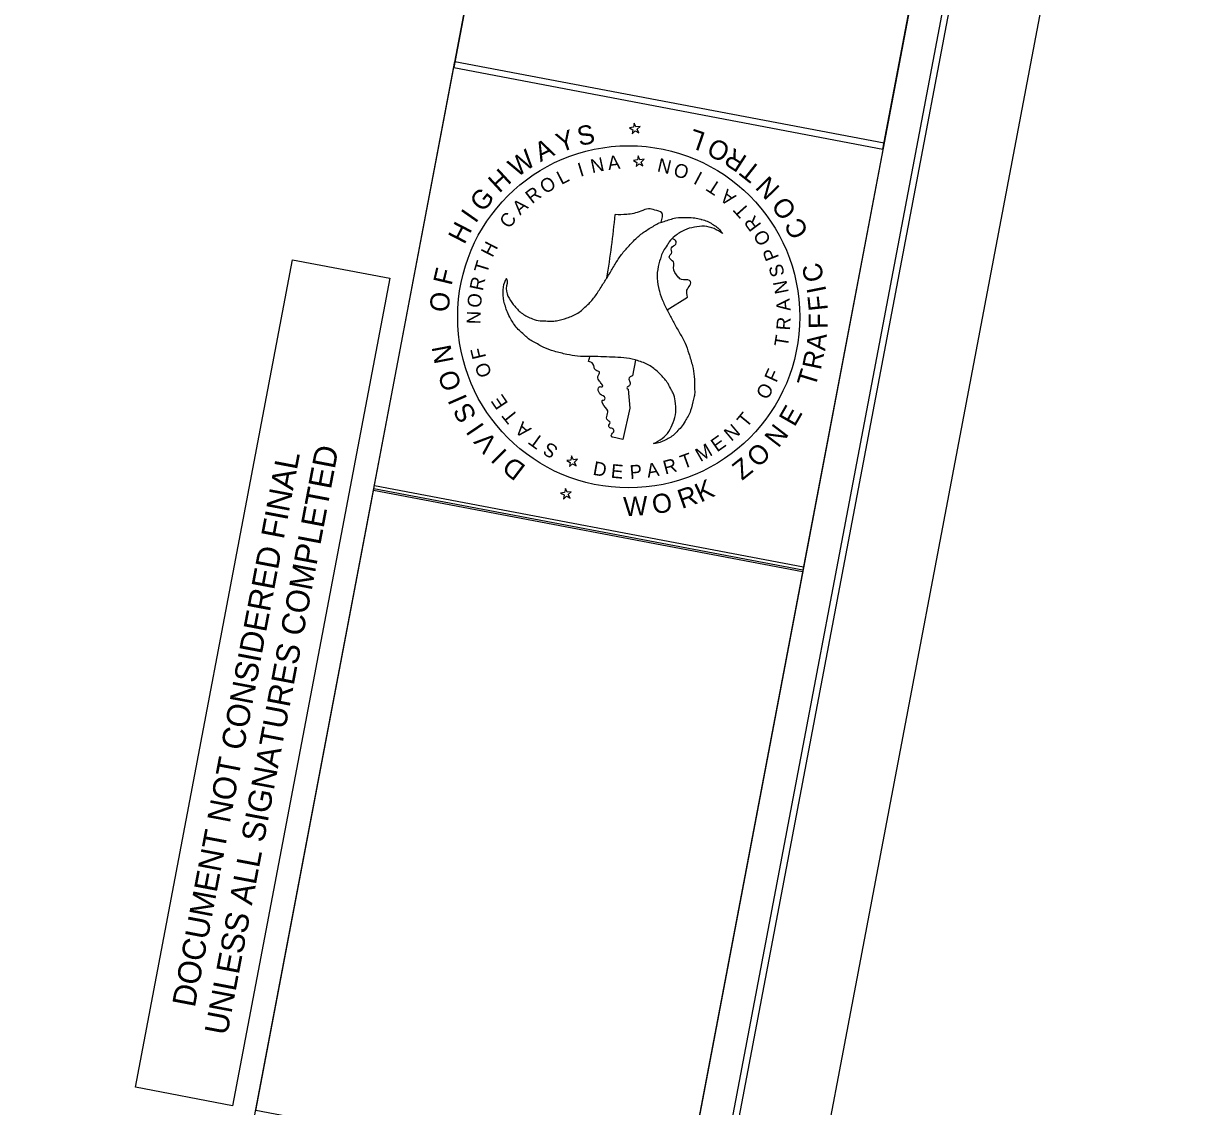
# Model space of a CAD drawing. Extents: x 1615680 to 1619687, y 899305 to 902270.
# Drawn here: x 1619375.5 to 1619686.6, y 901546.7 to 901831.9 of the extents above; entities that cross this region are included whole.
import ezdxf

# ---------------------------------------------------------------- set-up
doc = ezdxf.new("R2010")
doc.units = 0
for name, color, linetype in [('Prop Mkg Solid Yel Skip RT Rpm 80ft', 7, 'Continuous'), ('Scratch_Level_3', 7, 'Continuous'), ('Stage 5', 7, 'Continuous'), ('Stage 6', 7, 'Continuous')]:
    doc.layers.add(name, color=color, linetype=linetype)

msp = doc.modelspace()

# ---------------------------------------------------------------- linework, layer by layer
at = {"layer": 'Scratch_Level_3'}
for p, q in [((1619536.39, 901805.73), (1619536.19, 901804.66)), ((1619536.86, 901804.74), (1619536.39, 901805.73)), ((1619536.19, 901804.66), (1619535.13, 901804.49)), ((1619535.13, 901804.49), (1619536.06, 901803.99)), ((1619536.06, 901803.99), (1619535.86, 901802.92)), ((1619535.86, 901802.92), (1619536.66, 901803.67)), ((1619536.66, 901803.67), (1619537.62, 901803.16)), ((1619537.95, 901804.86), (1619536.86, 901804.74)), ((1619537.15, 901804.11), (1619537.95, 901804.86)), ((1619537.62, 901803.16), (1619537.15, 901804.11)), ((1619537.24, 901796.02), (1619536.19, 901795.85)), ((1619536.19, 901795.85), (1619537.12, 901795.34)), ((1619537.45, 901797.08), (1619537.24, 901796.02)), ((1619537.91, 901796.09), (1619537.45, 901797.08)), ((1619539, 901796.21), (1619537.91, 901796.09)), ((1619538.2, 901795.46), (1619539, 901796.21)), ((1619537.12, 901795.34), (1619536.91, 901794.28)), ((1619536.91, 901794.28), (1619537.71, 901795.02)), ((1619537.71, 901795.02), (1619538.68, 901794.51)), ((1619538.68, 901794.51), (1619538.2, 901795.46)), ((1619545.07, 901756.54), (1619550.47, 901759.91)), ((1619536.04, 901739.13), (1619536.86, 901743.28)), ((1619534.79, 901735.6), (1619535.28, 901730.6)), ((1619535.28, 901730.6), (1619533.41, 901722.4)), ((1619533.41, 901722.4), (1619530.81, 901722.98)), ((1619519.9, 901718.03), (1619519.7, 901716.96)), ((1619520.37, 901717.04), (1619519.9, 901718.03)), ((1619519.7, 901716.96), (1619518.64, 901716.79)), ((1619518.64, 901716.79), (1619519.57, 901716.29)), ((1619519.57, 901716.29), (1619519.37, 901715.22)), ((1619519.37, 901715.22), (1619520.16, 901715.97)), ((1619520.16, 901715.97), (1619521.13, 901715.46)), ((1619521.45, 901717.16), (1619520.37, 901717.04)), ((1619520.66, 901716.41), (1619521.45, 901717.16)), ((1619521.13, 901715.46), (1619520.66, 901716.41)), ((1619518.26, 901709.49), (1619518.06, 901708.42)), ((1619518.73, 901708.5), (1619518.26, 901709.49)), ((1619518.73, 901708.5), (1619518.26, 901709.49)), ((1619519.82, 901708.62), (1619518.73, 901708.5)), ((1619519.82, 901708.62), (1619518.73, 901708.5)), ((1619519.02, 901707.87), (1619519.82, 901708.62)), ((1619519.02, 901707.87), (1619519.82, 901708.62)), ((1619518.06, 901708.42), (1619517, 901708.25)), ((1619517, 901708.25), (1619517.93, 901707.75)), ((1619517.93, 901707.75), (1619517.73, 901706.68)), ((1619517.73, 901706.68), (1619518.53, 901707.43)), ((1619517.73, 901706.68), (1619518.53, 901707.43)), ((1619518.53, 901707.43), (1619519.5, 901706.92)), ((1619518.53, 901707.43), (1619519.5, 901706.92)), ((1619519.5, 901706.92), (1619519.02, 901707.87)), ((1619519.5, 901706.92), (1619519.02, 901707.87))]:
    msp.add_line(p, q, dxfattribs=at)
msp.add_circle((1619534.96, 901754.69), 45.07, dxfattribs=at)
for start, end in [(350.4529, 354.5729), (344.9279, 345.2256)]:
    msp.add_arc((1619298.76, 901803.71), 233.68, start, end, dxfattribs=at)
for points in [[(1619502.64, 901764.83), (1619502.71, 901764.74), (1619502.7, 901762.11), (1619503.45, 901759.58), (1619504.91, 901757.47), (1619506.93, 901755.53), (1619509.57, 901754.15), (1619511.63, 901753.62), (1619512.67, 901753.62), (1619514.46, 901753.53), (1619515.91, 901753.66), (1619518.71, 901754.42), (1619521.52, 901755.66), (1619524.02, 901757.76), (1619524.22, 901757.94), (1619526.16, 901760.2), (1619527.86, 901762.81), (1619529.43, 901765.3), (1619531, 901767.94), (1619532.64, 901770.52), (1619534.49, 901772.8), (1619536.82, 901775.24), (1619539.06, 901777.08), (1619541.69, 901778.72), (1619543.01, 901779.45), (1619544.29, 901779.84), (1619547.34, 901780.74), (1619550.48, 901780.86), (1619552.37, 901780.74), (1619553.95, 901780.39), (1619554.22, 901780.34), (1619556.97, 901779.13), (1619559.16, 901777.38), (1619559.7, 901776.62)], [(1619543.49, 901779.62), (1619543.65, 901782.11), (1619541.8, 901782.83), (1619540.19, 901783.16), (1619538.13, 901782.52), (1619534.43, 901781.67), (1619531.39, 901781.61)], [(1619559.7, 901776.62), (1619557.43, 901777.92), (1619554.89, 901778.54), (1619552.3, 901778.32), (1619549.61, 901777.54), (1619547.12, 901775.96), (1619545.62, 901774.44), (1619545.09, 901773.53), (1619544.1, 901772.07), (1619543.51, 901770.68), (1619542.74, 901767.92), (1619542.43, 901764.83), (1619543, 901761.63), (1619543.06, 901761.37), (1619544.08, 901758.55), (1619545.45, 901755.8), (1619546.81, 901753.16), (1619548.33, 901750.49), (1619549.79, 901747.77), (1619550.8, 901745.03), (1619551.74, 901741.79), (1619552.21, 901738.93), (1619552.31, 901735.85), (1619552.3, 901734.32), (1619552, 901733.03), (1619551.25, 901729.97), (1619549.79, 901727.16), (1619548.75, 901725.6), (1619547.62, 901724.42), (1619547.45, 901724.21), (1619545.05, 901722.41), (1619542.45, 901721.4), (1619541.47, 901721.29)], [(1619550.47, 901759.91), (1619550.29, 901761.68), (1619551.08, 901762.97), (1619551.32, 901763.61), (1619551.01, 901764.25), (1619548.89, 901764.48), (1619548.01, 901765.14), (1619546.77, 901767.71), (1619546.72, 901769.16), (1619545.64, 901770.43), (1619545.75, 901770.84), (1619546.23, 901771.41), (1619546.22, 901772.88), (1619547.36, 901773.85), (1619547.43, 901774.53), (1619546.48, 901775.26)], [(1619541.47, 901721.29), (1619543.78, 901722.63), (1619545.56, 901724.51), (1619546.66, 901726.85), (1619547.35, 901729.59), (1619547.22, 901732.54), (1619546.63, 901734.6), (1619546.14, 901735.51), (1619545.32, 901737.09), (1619544.45, 901738.27), (1619542.43, 901740.35), (1619539.93, 901742.14), (1619536.88, 901743.27), (1619536.62, 901743.35), (1619533.66, 901743.88), (1619530.6, 901744.05), (1619527.63, 901744.18), (1619524.55, 901744.21), (1619521.5, 901744.3), (1619518.61, 901744.79), (1619515.34, 901745.61), (1619512.6, 901746.62), (1619509.87, 901748.1), (1619508.59, 901748.86), (1619507.61, 901749.76), (1619505.32, 901751.97), (1619503.64, 901754.62), (1619502.8, 901756.31), (1619502.33, 901757.85), (1619502.24, 901758.12), (1619501.88, 901761.09), (1619502.29, 901763.86), (1619502.71, 901764.74)], [(1619530.81, 901722.98), (1619530.54, 901722.94), (1619530.35, 901723.44), (1619531.08, 901724.57), (1619530.67, 901725.28), (1619530.14, 901725.35), (1619529.7, 901725.96), (1619530.03, 901726.76), (1619529.22, 901727.69), (1619529.16, 901728.42), (1619529.44, 901729.9), (1619528.02, 901731.98), (1619528.05, 901732.72), (1619528.56, 901732.83), (1619528.72, 901733.26), (1619527.43, 901734.31), (1619527.27, 901734.54), (1619526.97, 901735.98), (1619527.31, 901736.29), (1619527.97, 901736.28), (1619528.12, 901736.46), (1619527.9, 901736.96), (1619527.24, 901737.72), (1619526.86, 901738.94), (1619527.27, 901740.19), (1619526.26, 901740.62), (1619525.54, 901742.31), (1619524.99, 901742.73), (1619524.39, 901742.93)], [(1619536.04, 901739.13), (1619535.33, 901738.92), (1619535.01, 901738.29), (1619535.31, 901737.28), (1619535.16, 901736.62), (1619534.46, 901735.98), (1619534.79, 901735.6)]]:
    msp.add_spline(points, degree=3, dxfattribs=at)
at = {"layer": 'Stage 5'}
msp.add_lwpolyline([(1618277.81, 900596.04), (1618595.68, 902270.17), (1619686.64, 902063.03), (1619368.77, 900388.9)], close=True, dxfattribs=at)
at = {"layer": 'Stage 6'}
for p, q in [((1619404.98, 901551.7), (1619446.37, 901769.7)), ((1619446.38, 901769.7), (1619471.99, 901764.84)), ((1619471.98, 901764.84), (1619430.59, 901546.83)), ((1619467.81, 901709.47), (1619580.87, 901688.01)), ((1619430.59, 901546.83), (1619404.98, 901551.7))]:
    msp.add_line(p, q, dxfattribs=at)
for points in [[(1618300.12, 900599.5), (1618613.97, 902252.47), (1619660.79, 902053.71), (1619346.95, 900400.74)], [(1618615.64, 902240.02), (1618333.18, 900752.34), (1619374.55, 900554.62), (1619657.01, 902042.3)], [(1619436.39, 901543.98), (1619533.55, 902055.74), (1619646.62, 902034.27), (1619549.46, 901522.51)], [(1619533.31, 902054.43), (1619488.87, 901820.37), (1619601.93, 901798.9), (1619646.37, 902032.96)], [(1619467.71, 901708.94), (1619489.18, 901822), (1619602.24, 901800.54), (1619580.77, 901687.47)], [(1619436.7, 901545.61), (1619467.96, 901710.25), (1619581.02, 901688.78), (1619549.76, 901524.14)]]:
    msp.add_lwpolyline(points, close=True, dxfattribs=at)

# ---------------------------------------------------------------- texts
at = {"layer": 'Prop Mkg Solid Yel Skip RT Rpm 80ft'}
for s, rotation, p in [('L', 160.9615, (1619555.47, 901803.06)), ('O', 152.8217, (1619562.11, 901799.67)), ('R', 147.1239, (1619566.44, 901796.76)), ('T', 141.833, (1619570.19, 901793.67)), ('N', 134.1928, (1619575.06, 901788.64)), ('O', 126.053, (1619579.46, 901782.62)), ('C', 119.0972, (1619582.52, 901777.03)), ('C', 104.8156, (1619586.56, 901764.61)), ('I', 101.3192, (1619587.07, 901761.44)), ('F', 95.8989, (1619587.47, 901756.49)), ('F', 90.4785, (1619587.41, 901751.52)), ('A', 83.9667, (1619586.71, 901745.59)), ('R', 78.2689, (1619585.55, 901740.5)), ('T', 72.978, (1619584.03, 901735.89)), ('E', 60.1764, (1619578.65, 901725.49)), ('N', 52.5361, (1619574.38, 901719.94)), ('O', 44.3964, (1619569.06, 901714.71)), ('Z', 38.5691, (1619564.82, 901711.45)), ('K', 25.0644, (1619553.9, 901705.68)), ('R', 19.3666, (1619548.94, 901704.04)), ('W', 2.5043, (1619533.65, 901702.16)), ('O', 11.2268, (1619541.63, 901702.57))]:
    msp.add_text(s, height=5.05, rotation=rotation, dxfattribs=at).set_placement(p)
at = {"layer": 'Scratch_Level_3'}
for s, height, rotation, p in [('S', 5.05, 12.4743, (1619521.99, 901799.64)), ('Y', 5.05, 18.9977, (1619516.91, 901797.91)), ('W', 5.05, 35.0626, (1619505.52, 901791.3)), ('A', 5.05, 26.0256, (1619511.7, 901795.42)), ('N', 3.63, 12.1007, (1619525.33, 901792.51)), ('A', 3.63, 7.0227, (1619529.63, 901793.33)), ('N', 3.63, 166.9823, (1619546.5, 901795.79)), ('H', 5.05, 42.7126, (1619500.84, 901787.1)), ('L', 3.63, 27.335, (1619517.19, 901789.4)), ('I', 3.63, 17.1788, (1619522.19, 901791.56)), ('O', 3.63, 162.1763, (1619551.17, 901794.26)), ('I', 3.63, 152.0201, (1619554.67, 901792.49)), ('O', 3.63, 32.4131, (1619512.97, 901786.92)), ('T', 3.63, 146.942, (1619559.61, 901789.52)), ('G', 5.05, 50.7661, (1619496.57, 901782.04)), ('R', 3.63, 37.4912, (1619509.5, 901784.31)), ('A', 3.63, 141.8639, (1619563.46, 901786.51)), ('A', 3.63, 42.5693, (1619506.33, 901781.35)), ('T', 3.63, 131.7077, (1619566.99, 901782.83)), ('I', 5.05, 55.0534, (1619494.59, 901779.12)), ('C', 3.63, 52.7254, (1619503.47, 901777.71)), ('R', 3.63, 126.6297, (1619570.06, 901778.93)), ('H', 5.05, 62.7034, (1619491.63, 901773.57)), ('O', 3.63, 121.5516, (1619572.62, 901774.85)), ('H', 3.63, 62.8816, (1619499.06, 901770.15)), ('P', 3.63, 111.3954, (1619574.63, 901770.31)), ('F', 5.05, 76.5069, (1619488.26, 901762.75)), ('T', 3.63, 73.0378, (1619497.6, 901765.89)), ('S', 3.63, 106.3173, (1619576.13, 901765.81)), ('R', 3.63, 78.1158, (1619496.51, 901761.37)), ('N', 3.63, 101.2392, (1619577.15, 901761.12)), ('O', 5.05, 85.0143, (1619487.51, 901755.8)), ('O', 3.63, 83.1939, (1619495.95, 901756.92)), ('A', 3.63, 96.1611, (1619577.66, 901756.35)), ('N', 3.63, 88.272, (1619495.88, 901752.7)), ('R', 3.63, 86.005, (1619577.44, 901751.03)), ('T', 3.63, 80.9269, (1619576.84, 901746.57)), ('N', 5.05, 100.8354, (1619488.86, 901742.89)), ('F', 3.63, 103.5063, (1619497.41, 901744.02)), ('O', 5.05, 109.3428, (1619491.04, 901736.25)), ('O', 3.63, 108.5844, (1619498.94, 901739.44)), ('F', 3.63, 65.6926, (1619573.84, 901737.18)), ('O', 3.63, 60.6146, (1619571.46, 901732.61)), ('I', 5.05, 113.6302, (1619492.51, 901733.04)), ('E', 3.63, 123.8186, (1619503.3, 901731.87)), ('S', 5.05, 119.8342, (1619495.04, 901728.61)), ('T', 3.63, 128.8967, (1619506.03, 901728.44)), ('A', 3.63, 139.0529, (1619509.47, 901725.17)), ('T', 3.63, 50.4584, (1619565.97, 901725.28)), ('I', 5.05, 124.1215, (1619497.07, 901725.72)), ('N', 3.63, 40.3022, (1619561.99, 901721.71)), ('V', 5.05, 130.83, (1619500.66, 901721.53)), ('T', 3.63, 144.1309, (1619512.84, 901722.55)), ('S', 3.63, 149.209, (1619516.63, 901720.21)), ('M', 3.63, 30.146, (1619553.85, 901716.36)), ('E', 3.63, 35.2241, (1619558.24, 901718.93)), ('I', 5.05, 135.1173, (1619503.19, 901719.08)), ('T', 3.63, 19.9899, (1619549.33, 901714.55)), ('D', 5.05, 142.7084, (1619508.11, 901715.24)), ('D', 3.63, 349.5214, (1619525.33, 901713.11)), ('E', 3.63, 354.5995, (1619530.14, 901712.32)), ('P', 3.63, 4.7556, (1619535.37, 901711.94)), ('A', 3.63, 9.8337, (1619539.99, 901712.29)), ('R', 3.63, 14.9118, (1619544.57, 901713.12))]:
    msp.add_text(s, height=height, rotation=rotation, dxfattribs=at).set_placement(p)
at = {"layer": 'Stage 6'}
for s, p in [('DOCUMENT NOT CONSIDERED FINAL', (1619420.61, 901572.52)), ('UNLESS ALL SIGNATURES COMPLETED', (1619429.15, 901565.17))]:
    msp.add_text(s, height=6.1012, rotation=79.2494, dxfattribs=at).set_placement(p)

doc.saveas('drawing.dxf')
